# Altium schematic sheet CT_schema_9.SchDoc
size 278 x 170 mm
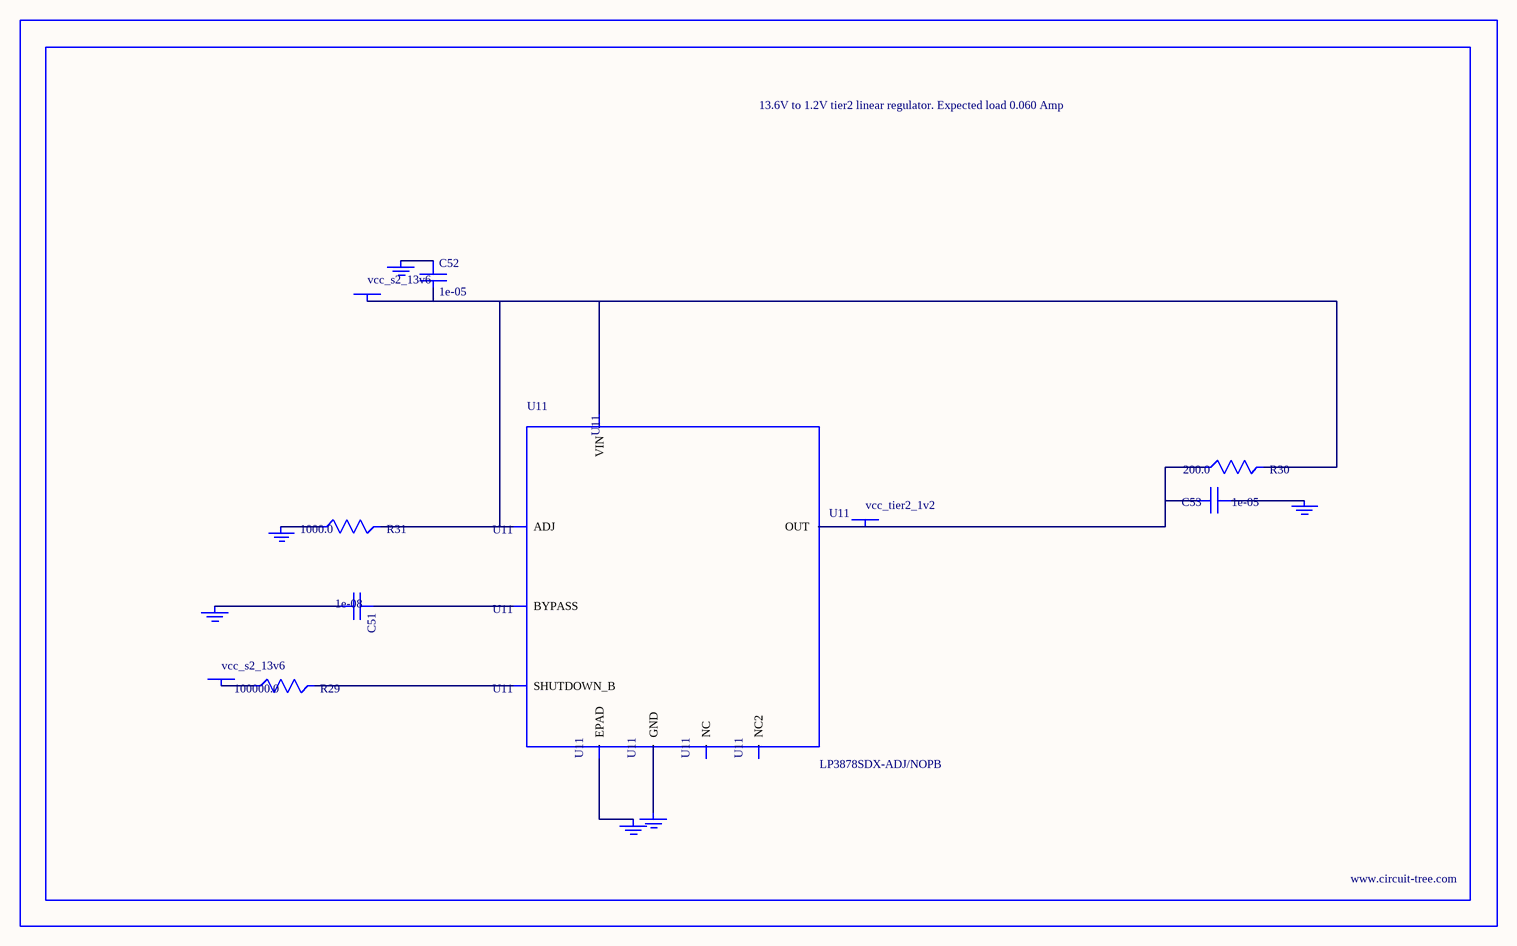
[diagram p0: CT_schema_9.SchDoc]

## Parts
BORDER8  (no value)
C51  1e-08  [C0402]
C52  1e-05  [C1210]
C53  1e-05  [C0805]
GND_INSTANCE_8_0  (no value)
GND_INSTANCE_8_1  (no value)
GND_INSTANCE_8_2  (no value)
GND_INSTANCE_8_3  (no value)
GND_INSTANCE_8_4  (no value)
GND_INSTANCE_8_5  (no value)
POWER_INSTANCE_8_0  vcc_s2_13v6
POWER_INSTANCE_8_1  vcc_s2_13v6
POWER_INSTANCE_8_2  vcc_tier2_1v2
R29  100000.0  [R0603]
R30  200.0  [R0603]
R31  1000.0  [R0603]
U11  LP3878SDX-ADJ/NOPB  [WSON-8]

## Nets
NetC51_1: C51.1 U11.1(BYPASS)
NetC51_2: C51.2 GND_INSTANCE_8_0.0(GND)
NetC52_1: C52.1 GND_INSTANCE_8_1.0(GND)
NetC52_2: C52.2 POWER_INSTANCE_8_0.0(PWR) R30.2 R31.2 U11.4(VIN) U11.6(ADJ)
NetC53_1: C53.1 GND_INSTANCE_8_2.0(GND)
NetC53_2: C53.2 POWER_INSTANCE_8_2.0(PWR) R30.1 U11.5(OUT)
NetGND_INSTANCE_8_3_0: GND_INSTANCE_8_3.0(GND) R31.1
NetGND_INSTANCE_8_4_0: GND_INSTANCE_8_4.0(GND) U11.PAD(EPAD)
NetGND_INSTANCE_8_5_0: GND_INSTANCE_8_5.0(GND) U11.3(GND)
NetPOWER_INSTANCE_8_1_0: POWER_INSTANCE_8_1.0(PWR) R29.1
NetR29_2: R29.2 U11.8(SHUTDOWN_B)

Not connected (* = marked no-connect by the designer): U11 2(NC) 7(NC2)

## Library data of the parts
BORDER8 = BORDER_PAGE8
C51 = C0402C103K3RAC
C52 = C1210C106K5PACTU
C53 = GRM219R60J106ME19D
GND_INSTANCE_8_0-GND_INSTANCE_8_5 = GND
POWER_INSTANCE_8_0-POWER_INSTANCE_8_2 = PWR
R29 = RC0603JR-07100KL
R30 = RC0603JR-07200RL
R31 = RC0603JR-071KL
